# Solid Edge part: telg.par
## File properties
Author: Georg
Template: Iso Part.par
Last saved by: Kalle
Revision: 4
Application: Solid Edge
Accuracy: 0,990
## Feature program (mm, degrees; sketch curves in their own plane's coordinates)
sketch for "unnamed Protrusion 1" plane through (0, 0, 0) normal (1, 0, 0) x-axis (0, 1, 0)
  circle centre (-21.6708, 15.199) radius 4
extrude "unnamed Protrusion 1" add finite 70 along +normal
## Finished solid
Body 1: solid body, 3 faces, 2 edges, 0 vertices.
  Faces by surface: plane 2, cylinder 1
  Edges by curve: circle 2
Bounding box of the edges (mm): 70.000 x 8.000 x 8.000, from (0, -25.6708, 11.199) to (70, -17.6708, 19.199).
Cylindrical faces by radius (mm): R4 x1
Planar faces by outward normal: +x 1, -x 1
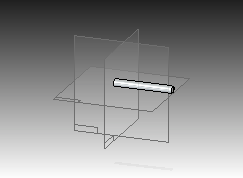
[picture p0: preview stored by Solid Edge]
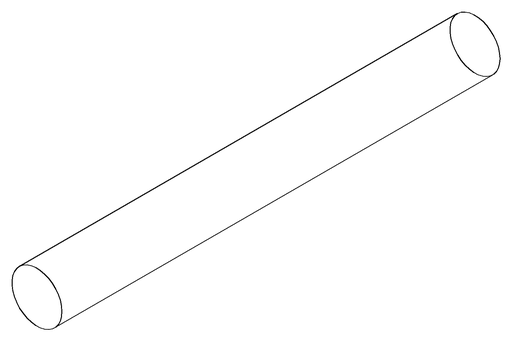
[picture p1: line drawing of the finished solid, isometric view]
